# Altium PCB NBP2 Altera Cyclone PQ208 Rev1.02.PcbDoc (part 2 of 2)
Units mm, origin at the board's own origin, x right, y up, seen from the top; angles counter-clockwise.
Board outline 69 x 80.99 mm, 2 copper layers (Top Layer, Bottom Layer); 52 components, 189 nets, 558 pads, 192 vias.
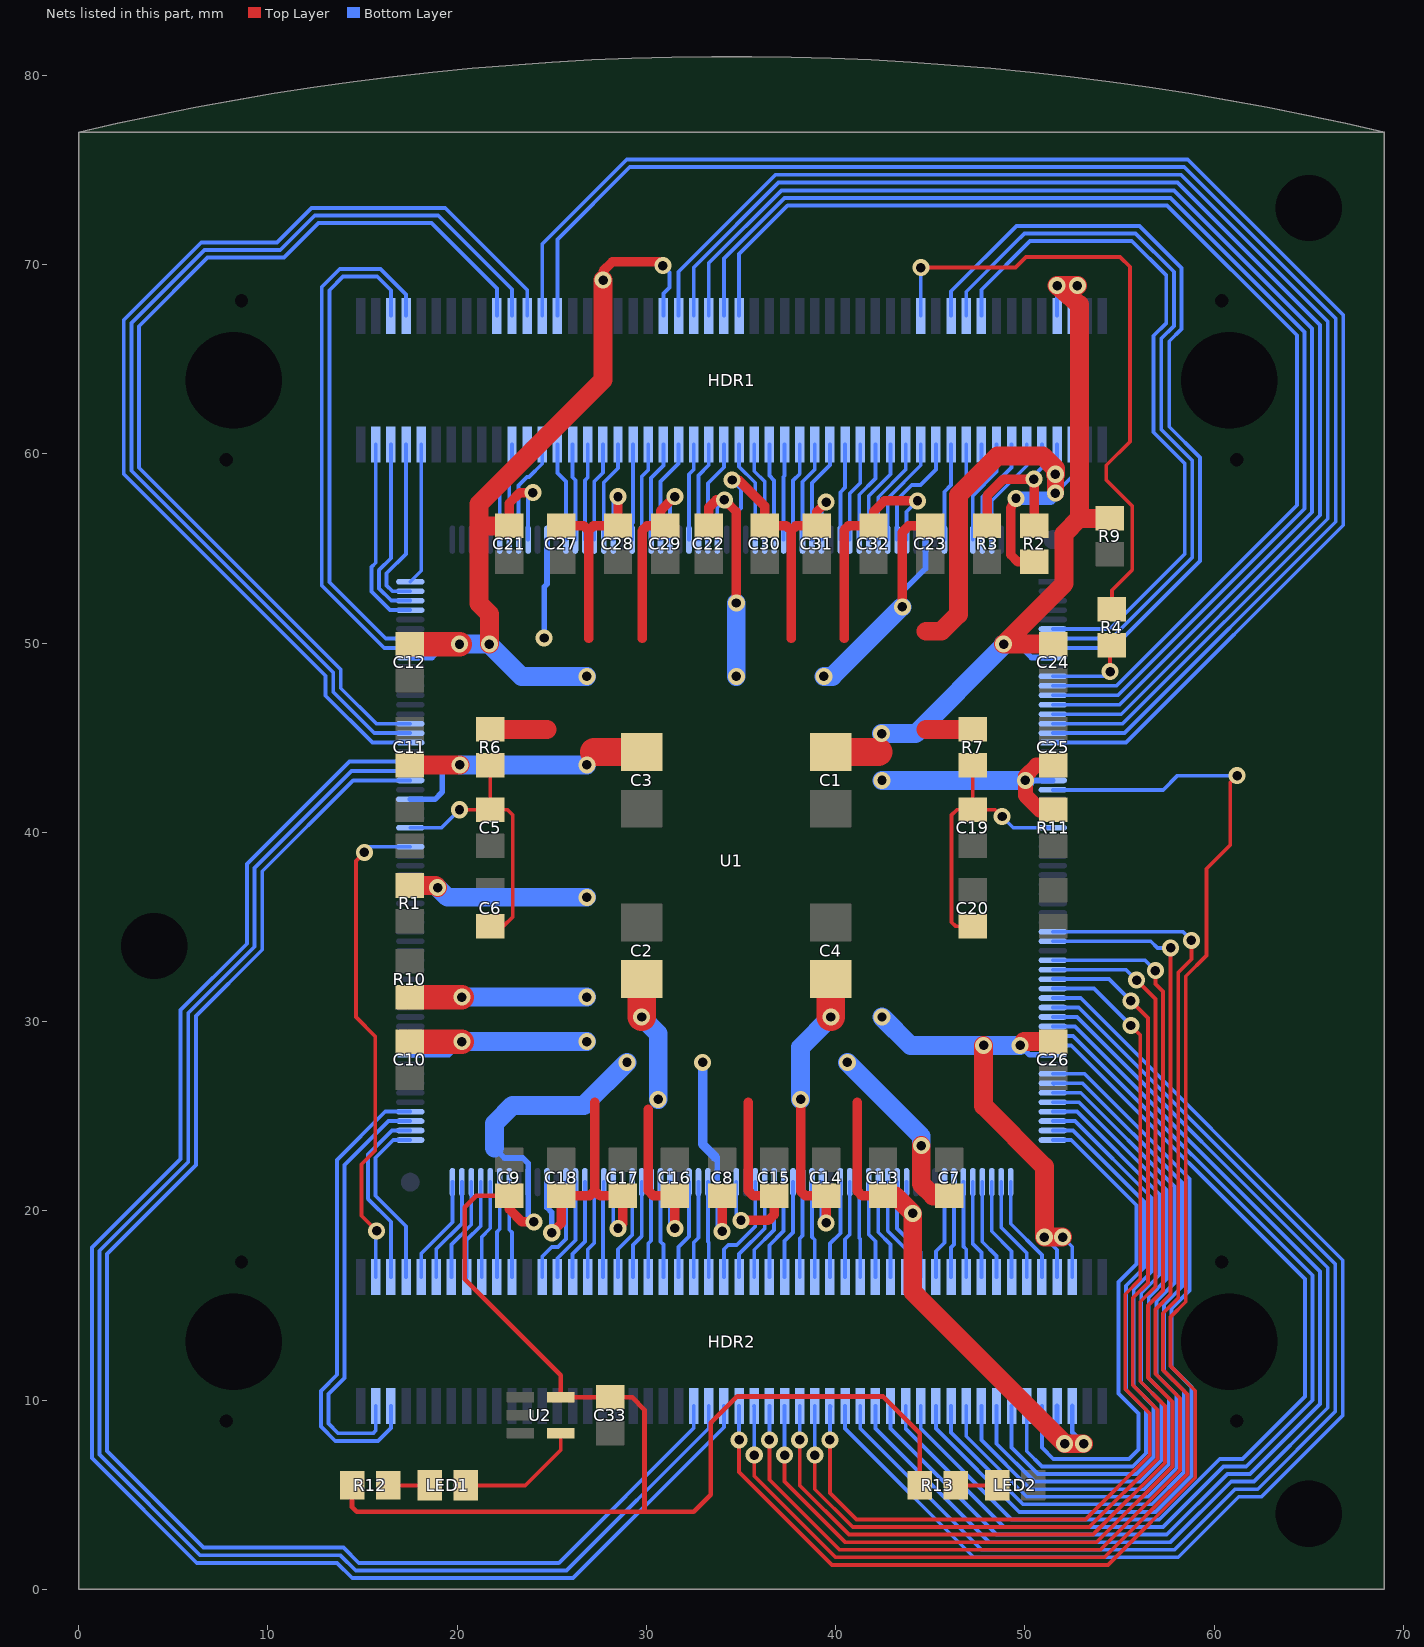
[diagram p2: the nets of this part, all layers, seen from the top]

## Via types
v1: diameter 0.9, hole 0.5, Top Layer to Bottom Layer, 192 vias

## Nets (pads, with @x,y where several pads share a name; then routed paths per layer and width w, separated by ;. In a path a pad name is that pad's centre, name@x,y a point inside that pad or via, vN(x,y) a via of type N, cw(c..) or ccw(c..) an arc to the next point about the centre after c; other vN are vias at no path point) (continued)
IO19: HDR2.45 U1.159 | length 81.4
  Bottom Layer w0.2: U1.159@17.525,42.75 14.505,42.75 9.703,37.948 9.703,33.803 6.198,30.297 6.198,22.431 1.5,17.734 1.5,7.314 6.598,2.216 13.989,2.216 14.805,1.4 25.375,1.4 32.5,8.525 HDR2.45@32.5,9.7
IO20: HDR2.47 U1.160 | length 83.8
  Bottom Layer w0.2: U1.160@17.525,43.25 14.421,43.25 9.296,38.125 9.296,33.962 5.791,30.457 5.791,22.591 1.1,17.9 1.1,7.13 6.426,1.803 13.836,1.803 14.64,1 25.781,1 33.3,8.519 HDR2.47@33.3,9.7
IO21: HDR2.49 U1.161 | length 86.1
  Bottom Layer w0.2: U1.161@17.525,43.75 14.311,43.75 8.89,38.329 8.89,34.121 5.385,30.616 5.385,22.75 0.7,18.065 0.7,6.945 6.242,1.403 13.659,1.403 14.462,0.6 26.127,0.6 34.1,8.573 HDR2.49@34.1,9.7
IO22: HDR2.51 U1.23 | length 80.7
  Top Layer w0.2: v1(34.9,7.9) 34.9,6.2 39.8,1.3 54.4,1.3 59,5.9 59,10.5 57.7,11.8 57.7,14.4 58.5,15.2 58.5,32.4 59.6,33.5 59.6,38.079 60.852,39.331 60.852,42.64 v1(61.214,43.002)
  Bottom Layer w0.2: v1(34.9,7.9) HDR2.51@34.9,9.7 ; U1.23@51.475,42.25 57.312,42.25 58.064,43.002 v1(61.214,43.002)
IO23: HDR2.53 U1.38 | length 67.1
  Top Layer w0.2: v1(35.7,7.1) 35.7,6 40,1.7 54.2,1.7 58.6,6.1 58.6,10.3 57.3,11.6 57.3,14.6 58.1,15.4 58.1,32.6 58.8,33.3 v1(58.8,34.3)
  Bottom Layer w0.2: HDR2.53@35.687,9.687 HDR2.53@35.7,9.7 v1(35.7,7.1) ; U1.38@51.475,34.75 58.35,34.75 v1(58.8,34.3)
IO24: HDR2.55 U1.39 | length 63.7
  Top Layer w0.2: v1(36.5,7.9) 36.5,5.8 40.2,2.1 54,2.1 58.2,6.3 58.2,10.1 56.9,11.4 56.9,14.8 57.7,15.6 v1(57.7,33.9)
  Bottom Layer w0.2: v1(36.5,7.9) HDR2.55@36.5,9.7 ; U1.39@51.475,34.25 56.65,34.25 57,33.9 v1(57.7,33.9)
IO25: HDR2.57 U1.41 | length 60.4
  Top Layer w0.2: v1(37.3,7.1) 37.3,5.7 40.5,2.5 53.8,2.5 57.8,6.5 57.8,9.9 56.5,11.2 56.5,15 57.3,15.8 57.3,31.6 56.9,32 v1(56.9,32.7)
  Bottom Layer w0.2: v1(37.3,7.1) HDR2.57@37.3,9.7 ; U1.41@51.475,33.25 56.35,33.25 v1(56.9,32.7)
IO26: HDR2.59 U1.42 | length 57.6
  Top Layer w0.2: v1(38.1,7.9) 38.1,5.5 40.7,2.9 53.6,2.9 57.4,6.7 57.4,9.7 56.1,11 56.1,15.2 56.9,16 56.9,31.2 v1(55.9,32.2)
  Bottom Layer w0.2: v1(38.1,7.9) HDR2.59@38.1,9.7 ; U1.42@51.475,32.75 55.35,32.75 v1(55.9,32.2)
IO27: HDR2.61 U1.43 | length 54.9
  Top Layer w0.2: v1(38.9,7.1) 38.9,5.3 40.9,3.3 53.4,3.3 57,6.9 57,9.5 55.7,10.8 55.7,15.4 56.5,16.2 56.5,30.2 v1(55.6,31.1)
  Bottom Layer w0.2: v1(38.9,7.1) HDR2.61@38.9,9.7 ; U1.43@51.475,32.25 54.45,32.25 v1(55.6,31.1)
IO28: HDR2.63 U1.44 | length 52.2
  Top Layer w0.2: v1(39.7,7.9) 39.7,5.1 41.1,3.7 53.2,3.7 56.6,7.1 56.6,9.3 55.3,10.6 55.3,15.6 56.1,16.4 56.1,29.3 v1(55.6,29.8)
  Bottom Layer w0.2: v1(39.7,7.9) HDR2.63@39.7,9.7 HDR2.63@39.725,9.675 ; U1.44@51.475,31.75 53.65,31.75 v1(55.6,29.8)
IO29: HDR2.65 U1.45 | length 62.7
  Bottom Layer w0.2: HDR2.65@40.5,9.7 40.5,8.5 47.3,1.7 58.1,1.7 61.3,4.9 62.5,4.9 66.8,9.2 66.8,17.4 52.95,31.25 U1.45@51.475,31.25
IO30: HDR2.67 U1.46 | length 60.3
  Bottom Layer w0.2: HDR2.67@41.3,9.7 41.3,8.5 47.7,2.1 57.9,2.1 61.1,5.3 62.3,5.3 66.4,9.4 66.4,17.2 52.85,30.75 U1.46@51.475,30.75
IO31: HDR2.69 U1.47 | length 57.9
  Bottom Layer w0.2: HDR2.69@42.1,9.7 42.1,8.5 48.1,2.5 57.7,2.5 60.9,5.7 62.1,5.7 66,9.6 66,17 52.75,30.25 U1.47@51.475,30.25
IO32: HDR2.71 U1.48 | length 55.6
  Bottom Layer w0.2: HDR2.71@42.9,9.7 42.9,8.5 48.5,2.9 57.5,2.9 60.7,6.1 61.9,6.1 65.6,9.8 65.6,16.8 52.65,29.75 U1.48@51.475,29.75
IO33: HDR2.73 U1.49 | length 53.2
  Bottom Layer w0.2: HDR2.73@43.7,9.7 43.7,8.5 48.9,3.3 57.3,3.3 60.5,6.5 61.7,6.5 65.2,10 65.2,16.6 52.55,29.25 U1.49@51.475,29.25
IO34: HDR2.75 U1.50 | length 50.8
  Bottom Layer w0.2: HDR2.75@44.5,9.7 44.5,8.5 49.3,3.7 57.1,3.7 60.3,6.9 61.5,6.9 64.8,10.2 64.8,16.4 52.45,28.75 U1.50@51.475,28.75
IO35: HDR2.77 U1.53 | length 43.4
  Bottom Layer w0.2: HDR2.77@45.3,9.7 45.3,8.5 49.7,4.1 56.9,4.1 58.8,6 58.8,10.7 57.75,11.75 57.75,14.85 58.7,15.8 58.7,21.7 53.15,27.25 U1.53@51.475,27.25
JIOA0: HDR1.3 U1.177 | length 10.3
  Bottom Layer w0.2: HDR1.3@15.7,60.5 15.7,54.252 15.475,54.027 15.475,52.725 16.45,51.75 U1.177@17.525,51.75
JIOA1: HDR1.5 U1.178 | length 9.8
  Bottom Layer w0.2: HDR1.5@16.5,60.5 16.5,54.486 15.875,53.861 15.875,52.891 16.516,52.25 U1.178@17.525,52.25
JIOA2: HDR1.7 U1.179 | length 9.2
  Bottom Layer w0.2: HDR1.7@17.3,60.5 17.3,54.721 16.275,53.696 16.275,53.056 16.581,52.75 U1.179@17.525,52.75
JIOA3: HDR1.9 U1.180 | length 7.5
  Bottom Layer w0.2: U1.180@17.525,53.25 18.1,53.825 HDR1.9@18.1,60.5
JIOB0: HDR1.83 U1.235 | length 5.4
  Bottom Layer w0.2: U1.235@46.75,55.475 46.75,57.872 47.7,58.822 HDR1.83@47.7,60.5
JIOB1: HDR1.85 U1.236 | length 5.5
  Bottom Layer w0.2: U1.236@47.25,55.475 47.25,57.806 48.5,59.056 HDR1.85@48.5,60.5
JIOB2: HDR1.87 U1.237 | length 5.7
  Bottom Layer w0.2: U1.237@47.75,55.475 47.75,57.74 49.3,59.291 HDR1.87@49.3,60.5
JIOB3: HDR1.89 U1.238 | length 5.8
  Bottom Layer w0.2: U1.238@48.25,55.475 48.25,57.525 50.1,59.375 HDR1.89@50.1,60.5
KBCLOCK: HDR1.22 U1.164 | length 54.4
  Bottom Layer w0.2: U1.164@17.525,45.25 15.625,45.25 13.45,47.425 13.45,48.447 2.788,59.109 2.788,66.919 6.644,70.775 10.65,70.775 12.475,72.6 19,72.6 22.9,68.7 HDR1.22@22.9,67.3
KBDATA: HDR1.24 U1.163 | length 56.7
  Bottom Layer w0.2: U1.163@17.525,44.75 15.525,44.75 13.05,47.225 13.05,48.281 2.388,58.943 2.388,67.085 6.478,71.175 10.484,71.175 12.309,73 19.375,73 23.7,68.675 HDR1.24@23.7,67.3
LCD_BCKL: HDR2.22 U1.114 | length 5.2
  Bottom Layer w0.2: U1.114@22.8,21.475 U1.114@22.75,21.525 22.75,19.006 22.9,18.856 HDR2.22@22.9,16.5
LCD_E: HDR2.26 U1.108 | length 5.7
  Bottom Layer w0.2: HDR2.26@24.5,16.5 24.5,17.6 25,18.1 25.325,18.1 25.75,18.525 U1.108@25.75,21.525
LED0: HDR2.60 U1.83 | length 5.1
  Bottom Layer w0.2: HDR2.60@38.1,16.5 38.1,18.55 38.25,18.7 U1.83@38.25,21.525
LED1: HDR2.62 U1.82 | length 5.1
  Bottom Layer w0.2: U1.82@38.75,21.525 38.75,18.625 38.9,18.475 HDR2.62@38.9,16.5
LED2: HDR2.64 U1.79 | length 5.3
  Bottom Layer w0.2: HDR2.64@39.7,16.5 39.7,18.275 40.25,18.825 U1.79@40.25,21.525
LED3: HDR2.66 U1.78 | length 5.1
  Bottom Layer w0.2: HDR2.66@40.5,16.5 40.5,18.509 40.75,18.759 U1.78@40.75,21.525
LED4: HDR2.68 U1.77 | length 5
  Bottom Layer w0.2: U1.77@41.25,21.525 41.25,18.575 41.3,18.525 HDR2.68@41.3,16.5
LED5: HDR2.70 U1.76 | length 5.2
  Bottom Layer w0.2: U1.76@41.75,21.525 41.75,18.75 42.1,18.4 HDR2.70@42.1,16.5
LED6: HDR2.72 U1.75 | length 5.3
  Bottom Layer w0.2: U1.75@42.25,21.525 42.25,18.875 42.9,18.225 HDR2.72@42.9,16.5
LED7: HDR2.74 U1.74 | length 5.4
  Bottom Layer w0.2: U1.74@42.75,21.525 42.75,18.95 43.7,18 HDR2.74@43.7,16.5
MOUSECLOCK: HDR1.26 U1.18 | length 82.6
  Bottom Layer w0.2: HDR1.26@24.5,67.3 24.5,71.1 28.959,75.559 58.604,75.559 66.825,67.338 66.825,56.233 55.342,44.75 U1.18@51.475,44.75
MOUSEDATA: HDR1.28 U1.17 | length 80.4
  Bottom Layer w0.2: HDR1.28@25.3,67.3 25.3,71.334 29.124,75.159 58.42,75.159 66.425,67.154 66.425,56.417 55.258,45.25 U1.17@51.475,45.25
NetC5_1: C5.1 C6.1 R6.2 U1.154 | length 15
  Top Layer w0.2: v1(20.125,41.2) C5.1@21.75,41.2 ; C6.1@21.75,35.05 22.452,35.05 22.936,35.535 22.936,40.919 22.656,41.2 C5.1@21.75,41.2 ; R6.2@21.75,43.55 C5.1@21.75,41.2
  Bottom Layer w0.2: U1.154@17.525,40.25 19.175,40.25 v1(20.125,41.2)
NetC19_2: C19.2 C20.2 R7.2 U1.27 | length 15.1
  Top Layer w0.2: C20.2@47.25,35.05 46.332,35.05 46.126,35.255 46.126,40.919 46.407,41.2 48.437,41.2 v1(48.793,40.843) ; C19.2@47.25,41.2 R7.2@47.25,43.55
  Bottom Layer w0.2: v1(48.793,40.843) 49.387,40.25 U1.27@51.475,40.25
NetLED1_1: LED1.1 R12.2 | length 2.2
  Top Layer w0.2: R12.2@16.35,5.5 LED1.1@18.55,5.5
NetLED1_2: LED1.2 U2.4 | length 6.7
  Top Layer w0.2: LED1.2@20.45,5.5 23.6,5.5 25.475,7.375 U2.4@25.475,8.25
NetLED2_1: LED2.1 R13.2 | length 2.2
  Top Layer w0.2: R13.2@46.35,5.5 LED2.1@48.55,5.5
NEXUS_TCK: HDR1.82 U1.7 | length 39.6
  Bottom Layer w0.2: HDR1.82@46.9,67.3 46.9,68.575 49.467,71.142 49.975,71.65 55.85,71.65 57.875,69.625 57.875,66.761 57.201,66.087 57.201,61.309 58.846,59.663 58.846,54.528 54.568,50.25 U1.7@51.475,50.25
NEXUS_TDI: HDR1.84 U1.6 | length 37.3
  Bottom Layer w0.2: HDR1.84@47.7,67.3 47.7,68.675 50.275,71.25 55.65,71.25 57.475,69.425 57.475,66.927 56.794,66.246 56.794,61.149 58.445,59.498 58.445,54.712 54.483,50.75 U1.6@51.475,50.75
NEXUS_TDO: HDR1.76 R4.2 | length 33.7
  Top Layer w0.2: v1(44.5,69.85) 49.507,69.85 50.066,70.409 55.033,70.409 55.55,69.892 55.55,60.65 54.3,59.4 54.3,58.628 55.677,57.252 55.677,53.877 54.6,52.8 R4.2@54.6,51.8
  Bottom Layer w0.2: HDR1.76@44.5,67.3 v1(44.5,69.85)
NEXUS_TDO#: R4.1 U1.11 | length 4.9
  Top Layer w0.2: v1(54.5,48.5) R4.1@54.5,50.3
  Bottom Layer w0.2: U1.11@51.475,48.25 54.25,48.25 v1(54.5,48.5)
NEXUS_TMS: HDR1.80 U1.8 | length 41.9
  Bottom Layer w0.2: HDR1.80@46.1,67.3 46.1,68.6 49.55,72.05 56.05,72.05 58.275,69.825 58.275,66.595 57.633,65.953 57.633,61.443 59.258,59.817 59.258,54.347 54.661,49.75 U1.8@51.475,49.75
RAM0_DATA0: HDR2.42 U1.98 | length 5.1
  Bottom Layer w0.2: U1.98@30.75,21.525 30.75,18.375 30.9,18.225 HDR2.42@30.9,16.5
RAM0_DATA1: HDR2.40 U1.99 | length 5.1
  Bottom Layer w0.2: HDR2.40@30.1,16.5 30.1,18.275 30.25,18.425 U1.99@30.25,21.525
RAM0_DATA2: HDR2.38 U1.100 | length 5.2
  Bottom Layer w0.2: HDR2.38@29.3,16.5 29.3,18.209 29.75,18.659 U1.100@29.75,21.525
RAM0_DATA3: HDR2.36 U1.101 | length 5.3
  Bottom Layer w0.2: HDR2.36@28.5,16.5 28.5,17.975 29.25,18.725 U1.101@29.25,21.525
RAM0_DATA4: HDR2.34 U1.104 | length 5
  Bottom Layer w0.2: HDR2.34@27.7,16.5 27.7,20.575 27.75,20.625 U1.104@27.75,21.525
RAM0_DATA5: HDR2.32 U1.105 | length 5.2
  Bottom Layer w0.2: HDR2.32@26.9,16.5 26.9,17.969 27.25,18.319 U1.105@27.25,21.525
RAM0_DATA6: HDR2.30 U1.106 | length 5.3
  Bottom Layer w0.2: HDR2.30@26.1,16.5 26.1,17.734 26.75,18.384 U1.106@26.75,21.525
RAM0_DATA7: HDR2.28 U1.107 | length 5.4
  Bottom Layer w0.2: HDR2.28@25.3,16.5 25.3,17.5 26.25,18.45 U1.107@26.25,21.525
RAM0_OE: HDR1.41 U1.202 | length 5.3
  Bottom Layer w0.2: U1.202@30.25,55.475 30.25,58.734 30.9,59.384 HDR1.41@30.9,60.5
RAM0_WE: HDR1.79 U1.233 | length 5.2
  Bottom Layer w0.2: U1.233@45.75,55.475 45.75,58.003 46.1,58.353 HDR1.79@46.1,60.5
RAM1_DATA0: HDR1.45 U1.206 | length 5.1
  Bottom Layer w0.2: U1.206@32.25,55.475 32.25,58.925 32.5,59.175 HDR1.45@32.5,60.5
RAM1_DATA1: HDR1.49 U1.208 | length 5.4
  Bottom Layer w0.2: U1.208@33.25,55.475 33.25,58.45 34.1,59.3 HDR1.49@34.1,60.5
RAM1_DATA2: HDR1.53 U1.214 | length 5.3
  Bottom Layer w0.2: HDR1.53@35.7,60.5 35.7,59.091 36.25,58.541 U1.214@36.25,55.475
RAM1_DATA3: HDR1.57 U1.216 | length 5
  Bottom Layer w0.2: U1.216@37.25,55.475 37.25,58.8 37.3,58.85 HDR1.57@37.3,60.5
RAM1_DATA4: HDR1.55 U1.215 | length 5.1
  Bottom Layer w0.2: HDR1.55@36.5,60.5 36.5,58.856 36.75,58.606 U1.215@36.75,55.475
RAM1_DATA5: HDR1.51 U1.213 | length 5.4
  Bottom Layer w0.2: HDR1.51@34.9,60.5 34.9,59.325 35.75,58.475 U1.213@35.75,55.475
RAM1_DATA6: HDR1.47 U1.207 | length 5.3
  Bottom Layer w0.2: U1.207@32.75,55.475 32.75,58.859 33.3,59.409 HDR1.47@33.3,60.5
RAM1_DATA7: HDR1.43 U1.203 | length 5.4
  Bottom Layer w0.2: U1.203@30.75,55.475 30.75,58.55 31.7,59.5 HDR1.43@31.7,60.5
RAM1_OE: HDR1.39 U1.201 | length 5.2
  Bottom Layer w0.2: U1.201@29.75,55.475 29.75,58.8 30.1,59.15 HDR1.39@30.1,60.5
RAM1_WE: HDR1.61 U1.218 | length 5.3
  Bottom Layer w0.2: U1.218@38.25,55.475 38.25,58.534 38.9,59.184 HDR1.61@38.9,60.5
RAM_ADDR0: HDR1.21 U1.186 | length 5.3
  Bottom Layer w0.2: U1.186@22.25,55.475 22.25,58.639 22.9,59.289 HDR1.21@22.9,60.5
RAM_ADDR1: HDR1.25 U1.188 | length 5.6
  Bottom Layer w0.2: U1.188@23.25,55.475 23.25,58.338 23.697,58.786 23.799,58.786 24.5,59.487 HDR1.25@24.5,60.5
RAM_ADDR2: HDR1.29 U1.194 | length 5.1
  Bottom Layer w0.2: HDR1.29@26.1,60.5 26.1,58.766 26.25,58.616 U1.194@26.25,55.475
RAM_ADDR3: HDR1.33 U1.196 | length 5.2
  Bottom Layer w0.2: U1.196@27.25,55.475 27.25,58.557 27.7,59.007 HDR1.33@27.7,60.5
RAM_ADDR4: HDR1.65 U1.222 | length 5.1
  Bottom Layer w0.2: U1.222@40.25,55.475 40.25,57.978 40.5,58.228 HDR1.65@40.5,60.5
RAM_ADDR5: HDR1.69 U1.224 | length 5.4
  Bottom Layer w0.2: U1.224@41.25,55.475 41.25,57.847 42.1,58.697 HDR1.69@42.1,60.5
RAM_ADDR6: HDR1.73 U1.226 | length 5.6
  Bottom Layer w0.2: U1.226@42.25,55.475 42.25,57.716 43.7,59.166 HDR1.73@43.7,60.5
RAM_ADDR7: HDR1.77 U1.228 | length 6.1
  Bottom Layer w0.2: U1.228@43.25,55.475 43.25,57.58 44.025,58.355 44.48,58.355 45.3,59.175 HDR1.77@45.3,60.5
RAM_ADDR8: HDR1.75 U1.227 | length 5.7
  Bottom Layer w0.2: U1.227@42.75,55.475 42.75,57.65 44.5,59.4 HDR1.75@44.5,60.5
RAM_ADDR9: HDR1.71 U1.225 | length 5.5
  Bottom Layer w0.2: U1.225@41.75,55.475 41.75,57.781 42.9,58.931 HDR1.71@42.9,60.5
RAM_ADDR10: HDR1.67 U1.223 | length 5.3
  Bottom Layer w0.2: U1.223@40.75,55.475 40.75,57.913 41.3,58.463 HDR1.67@41.3,60.5
RAM_ADDR11: HDR1.63 U1.219 | length 5.4
  Bottom Layer w0.2: U1.219@38.75,55.475 38.75,58.469 39.7,59.419 HDR1.63@39.7,60.5
RAM_ADDR12: HDR1.59 U1.217 | length 5.2
  Bottom Layer w0.2: U1.217@37.75,55.475 37.75,58.6 38.1,58.95 HDR1.59@38.1,60.5
RAM_ADDR13: HDR1.35 U1.197 | length 5.3
  Bottom Layer w0.2: U1.197@27.75,55.475 27.75,58.491 28.5,59.241 HDR1.35@28.5,60.5
RAM_ADDR14: HDR1.31 U1.195 | length 5.1
  Bottom Layer w0.2: U1.195@26.75,55.475 26.75,58.6 26.9,58.75 HDR1.31@26.9,60.5
RAM_ADDR15: HDR1.27 U1.193 | length 5.2
  Bottom Layer w0.2: HDR1.27@25.3,60.5 25.3,59 25.75,58.55 U1.193@25.75,55.475
RAM_ADDR16: HDR1.23 U1.187 | length 5.4
  Bottom Layer w0.2: U1.187@22.75,55.475 22.75,58.486 23.7,59.436 HDR1.23@23.7,60.5
RAM_CS: HDR1.37 U1.200 | length 5
  Bottom Layer w0.2: U1.200@29.25,55.475 29.25,56.325 29.3,56.375 HDR1.37@29.3,60.5
RED0: HDR1.6 U1.174 | length 26.1
  Bottom Layer w0.2: HDR1.6@16.5,67.3 16.5,68.65 15.775,69.375 13.975,69.375 13.25,68.65 13.25,53.225 16.225,50.25 U1.174@17.525,50.25
RED1: HDR1.8 U1.173 | length 28.3
  Bottom Layer w0.2: HDR1.8@17.3,67.3 17.3,68.425 15.95,69.775 13.8,69.775 12.85,68.825 12.85,53.05 16.15,49.75 U1.173@17.525,49.75
REF_CLK: HDR2.4 U1.152 | length 26.3
  Top Layer w0.2: v1(15.1,38.95) 14.65,38.5 14.65,30.245 15.672,29.224 15.672,23.19 14.948,22.466 14.948,19.752 v1(15.75,18.95)
  Bottom Layer w0.2: v1(15.1,38.95) 15.35,39.25 U1.152@17.525,39.25 ; HDR2.4@15.7,16.5 15.7,18.9 v1(15.75,18.95)
SCL: HDR2.5 U1.124 | length 24.8
  Bottom Layer w0.2: HDR2.5@16.5,9.7 16.5,8.525 15.821,7.846 13.561,7.846 12.8,8.606 12.8,10.493 13.65,11.343 13.65,22.7 16.2,25.25 U1.124@17.525,25.25
SDA: HDR2.3 U1.123 | length 22.5
  Bottom Layer w0.2: HDR2.3@15.7,9.7 15.7,8.4 15.55,8.25 13.722,8.25 13.2,8.772 13.2,10.328 14.05,11.178 14.05,22.425 16.375,24.75 U1.123@17.525,24.75
SP0: HDR2.79 U1.54 | length 41.2
  Bottom Layer w0.2: HDR2.79@46.1,9.7 46.1,8.3 49.9,4.5 56.7,4.5 58.4,6.2 58.4,10.5 57.35,11.55 57.35,15.05 58.3,16 58.3,21.5 53.05,26.75 U1.54@51.475,26.75 U1.54@51.525,26.7
SP1: HDR2.81 U1.55 | length 38.9
  Bottom Layer w0.2: HDR2.81@46.9,9.7 46.9,8.1 50.1,4.9 56.5,4.9 58,6.4 58,10.3 56.95,11.35 56.95,15.25 57.9,16.2 57.9,21.3 52.95,26.25 U1.55@51.475,26.25
SP2: HDR2.83 U1.56 | length 36.6
  Bottom Layer w0.2: HDR2.83@47.7,9.7 47.7,7.9 50.3,5.3 56.3,5.3 57.6,6.6 57.6,10.1 56.55,11.15 56.55,15.45 57.5,16.4 57.5,21.1 52.85,25.75 U1.56@51.475,25.75
SP3: HDR2.85 U1.57 | length 34.3
  Bottom Layer w0.2: HDR2.85@48.5,9.7 48.5,7.7 50.5,5.7 56.1,5.7 57.2,6.8 57.2,9.9 56.15,10.95 56.15,15.65 57.1,16.6 57.1,20.9 52.75,25.25 U1.57@51.475,25.25
SP4: HDR2.87 U1.58 | length 32.1
  Bottom Layer w0.2: HDR2.87@49.3,9.7 49.3,7.5 50.7,6.1 55.9,6.1 56.8,7 56.8,9.7 55.75,10.75 55.75,15.85 56.7,16.8 56.7,20.7 52.65,24.75 U1.58@51.475,24.75
SP5: HDR2.89 U1.59 | length 29.8
  Bottom Layer w0.2: HDR2.89@50.1,9.7 50.1,7.3 50.9,6.5 55.7,6.5 56.4,7.2 56.4,9.5 55.35,10.55 55.35,16.05 56.3,17 56.3,20.5 52.55,24.25 U1.59@51.475,24.25
SP6: HDR2.91 U1.60 | length 27.3
  Bottom Layer w0.2: HDR2.91@50.9,9.7 50.9,7.5 51.5,6.9 55.5,6.9 56,7.4 56,9.3 54.95,10.35 54.95,16.25 55.9,17.2 55.9,20.3 52.45,23.75 U1.60@51.475,23.75
SP7: HDR2.92 U1.61 | length 5.7
  Bottom Layer w0.2: U1.61@49.25,21.525 49.25,19.325 50.9,17.675 HDR2.92@50.9,16.5
SP8: HDR2.90 U1.62 | length 5.6
  Bottom Layer w0.2: U1.62@48.75,21.525 48.75,19.125 50.1,17.775 HDR2.90@50.1,16.5
SP9: HDR2.88 U1.63 | length 5.5
  Bottom Layer w0.2: U1.63@48.25,21.525 48.25,18.925 49.3,17.875 HDR2.88@49.3,16.5
SP10: HDR2.86 U1.64 | length 5.3
  Bottom Layer w0.2: U1.64@47.75,21.525 47.75,18.375 48.5,17.625 HDR2.86@48.5,16.5
SP11: HDR2.84 U1.65 | length 5.2
  Bottom Layer w0.2: U1.65@47.25,21.525 47.25,18.25 47.7,17.8 HDR2.84@47.7,16.5
SP12: HDR2.82 U1.66 | length 5.1
  Bottom Layer w0.2: U1.66@46.75,21.525 46.75,18.125 46.9,17.975 HDR2.82@46.9,16.5
SP13: HDR2.80 U1.67 | length 5.1
  Bottom Layer w0.2: HDR2.80@46.1,16.5 46.1,18.075 46.25,18.225 U1.67@46.25,21.525
SP14: HDR2.78 U1.68 | length 5.2
  Bottom Layer w0.2: HDR2.78@45.3,16.5 45.3,17.875 45.75,18.325 U1.68@45.75,21.525
SP15: HDR2.76 U1.73 | length 5.5
  Bottom Layer w0.2: U1.73@43.25,21.525 43.25,19.075 44.5,17.825 HDR2.76@44.5,16.5
SPI_CLK: HDR1.46 U1.15 | length 69.2
  Bottom Layer w0.2: HDR1.46@32.5,67.3 32.5,69.859 36.986,74.346 58.064,74.346 65.6,66.81 65.6,56.761 55.089,46.25 U1.15@51.475,46.25
SPI_DIN: HDR1.44 U1.16 | length 71.4
  Bottom Layer w0.2: HDR1.44@31.7,67.3 31.7,69.625 36.827,74.752 58.242,74.752 66,66.994 66,56.577 55.173,45.75 U1.16@51.475,45.75
SPI_DOUT: HDR1.50 U1.13 | length 64.7
  Bottom Layer w0.2: HDR1.50@34.1,67.3 34.1,70.328 37.299,73.527 57.69,73.527 64.775,66.441 64.775,57.104 54.921,47.25 U1.13@51.475,47.25
SPI_MODE: HDR1.52 U1.12 | length 62.5
  Bottom Layer w0.2: HDR1.52@34.9,67.3 34.9,70.562 37.464,73.127 57.517,73.127 64.375,66.269 64.375,57.288 54.837,47.75 U1.12@51.475,47.75
SPI_SEL: HDR1.48 U1.14 | length 66.9
  Bottom Layer w0.2: HDR1.48@33.3,67.3 33.3,70.094 37.133,73.927 57.874,73.927 65.175,66.626 65.175,56.92 55.005,46.75 U1.14@51.475,46.75
SW0: HDR2.44 U1.95 | length 5.3
  Bottom Layer w0.2: HDR2.44@31.7,16.5 31.7,18.1 32.25,18.65 U1.95@32.25,21.525
SW1: HDR2.46 U1.94 | length 5.1
  Bottom Layer w0.2: HDR2.46@32.5,16.5 32.5,18.334 32.75,18.584 U1.94@32.75,21.525
SW2: HDR2.48 U1.93 | length 5
  Bottom Layer w0.2: U1.93@33.25,21.525 33.25,18.375 33.3,18.325 HDR2.48@33.3,16.5
SW3: HDR2.50 U1.88 | length 6
  Bottom Layer w0.2: HDR2.50@34.1,16.5 34.1,17.975 34.325,18.2 34.775,18.2 35.75,19.175 U1.88@35.75,21.525
SW4: HDR2.52 U1.87 | length 5.6
  Bottom Layer w0.2: HDR2.52@34.9,16.5 34.9,17.725 36.25,19.075 U1.87@36.25,21.525
SW5: HDR2.54 U1.86 | length 5.5
  Bottom Layer w0.2: HDR2.54@35.7,16.5 35.7,17.95 36.75,19 U1.86@36.75,21.525
SW6: HDR2.56 U1.85 | length 5.3
  Bottom Layer w0.2: HDR2.56@36.5,16.5 36.5,18.184 37.25,18.934 U1.85@37.25,21.525
SW7: HDR2.58 U1.84 | length 5.2
  Bottom Layer w0.2: HDR2.58@37.3,16.5 37.3,18.419 37.75,18.869 U1.84@37.75,21.525
SWC0: HDR2.18 U1.116 | length 5.2
  Bottom Layer w0.2: HDR2.18@21.3,16.5 21.3,18.633 21.75,19.083 U1.116@21.75,21.525
SWC1: HDR2.16 U1.117 | length 5.3
  Bottom Layer w0.2: HDR2.16@20.5,16.5 20.5,18.46 21.25,19.21 U1.117@21.25,21.525
SWC2: HDR2.14 U1.118 | length 5.5
  Bottom Layer w0.2: HDR2.14@19.7,16.5 19.7,18.226 20.75,19.276 U1.118@20.75,21.525
SWC3: HDR2.6 U1.122 | length 9.7
  Bottom Layer w0.2: HDR2.6@16.5,16.5 16.5,19.431 15.291,20.64 15.291,22.981 16.559,24.25 U1.122@17.525,24.25
SWR0: HDR2.20 U1.115 | length 5.1
  Bottom Layer w0.2: HDR2.20@22.1,16.5 22.1,18.889 22.25,19.039 U1.115@22.25,21.525
SWR1: HDR2.12 U1.119 | length 5.6
  Bottom Layer w0.2: HDR2.12@18.9,16.5 18.9,17.991 20.25,19.341 U1.119@20.25,21.525
SWR2: HDR2.10 U1.120 | length 5.7
  Bottom Layer w0.2: HDR2.10@18.1,16.5 18.1,17.757 19.75,19.407 U1.120@19.75,21.525
SWR3: HDR2.8 U1.121 | length 9.2
  Bottom Layer w0.2: HDR2.8@17.3,16.5 17.3,19.197 15.691,20.806 15.691,22.816 16.625,23.75 U1.121@17.525,23.75
TEST: HDR1.81 U1.234 | length 5.3
  Bottom Layer w0.2: U1.234@46.25,55.475 46.25,57.938 46.9,58.588 HDR1.81@46.9,60.5
VCC: C1.1 C3.1 C7.1 C8.1 C9.1 C10.1 C11.1 C12.1 C21.2 C22.2 C23.2 C24.2 C25.2 C26.2 C33.1 HDR1.34 HDR1.42 HDR1.94 HDR1.96 HDR2.94 HDR2.96 R1.1 R9.1 R10.1 R11.1 R12.1 R13.1 U1.9 U1.22 U1.51 U1.70 U1.92 U1.112 U1.130 U1.157 U1.172 U1.189 U1.209 U1.231 U2.5 | length 317.7
  Top Layer w0.25: R12.1@14.45,5.5 14.45,4.35 14.7,4.1 32.5,4.1 33.4,5 33.4,8.8 34.8,10.2 42.5,10.2 44.45,8.25 R13.1@44.45,5.5 ; C9.1@22.75,20.8 21,20.8 20.4,20.2 20.4,16.4 25.475,11.325 U2.5@25.475,10.15 29.25,10.15 29.9,9.5 29.9,4.1
  Top Layer w0.5: C9.1@22.75,20.8 22.75,20.1 23.425,19.425 v1(24.05,19.425) ; C21.2@22.75,56.2 22.75,57.396 23.317,57.963 v1(24.003,57.963) ; v1(27.711,69.19) 27.711,69.667 28.194,70.15 30.675,70.15 v1(30.875,69.95) ; C22.2@33.3,56.2 33.3,57.175 33.7,57.575 v1(34.125,57.575) 34.75,56.95 v1(34.75,52.125) ; v1(34,18.925) C8.1@34,20.8 ; v1(43.525,51.925) 43.525,55.875 43.85,56.2 C23.2@45,56.2
  Top Layer w0.8: R11.1@51.5,41.2 50.775,41.2 50.025,41.95 50.025,42.975 50.6,43.55 C25.2@51.5,43.55
  Top Layer w1: R1.1@17.5,37.2 18.858,37.2 v1(18.974,37.084) ; C11.1@17.5,43.55 17.525,43.575 v1(20.15,43.575) ; 21.15,56.2 C21.2@22.75,56.2 ; v1(21.7,49.95) 21.7,51.55 21.15,52.1 21.15,57.353 27.711,63.915 v1(27.711,69.19) ; v1(44.525,23.45) 44.525,21.425 45.15,20.8 C7.1@46,20.8 ; v1(47.821,28.746) 47.821,25.554 51.029,22.346 v1(51.029,18.618) v1(51.994,18.618) ; v1@49.95,28.95 C26.2@51.5,28.95 ; C24.2@51.5,49.95 v1(48.875,49.95) 52.07,53.145 52.07,54.559 52.07,55.778 52.883,56.591 ; v1(52.775,68.9) v1(51.7,68.9) 52.883,67.894 52.883,56.591 ; R9.1@54.483,56.601 52.883,56.591
  Top Layer w1.3: C10.1@17.5,28.95 v1(20.25,28.95) ; R10.1@17.5,31.3 v1(20.25,31.3) ; C12.1@17.5,49.95 v1(20.125,49.95)
  Top Layer w1.5: 27.25,44.25 C3.1@29.75,44.25 ; C1.1@39.75,44.25 42.25,44.25
  Bottom Layer w0.2: U1.189@23.75,55.475 23.75,57.71 v1(24.003,57.963) ; HDR1.34@27.7,67.3 27.7,69.325 v1(27.711,69.19) ; v1(30.875,69.95) 31.225,69.6 31.225,68.8 30.9,68.475 HDR1.42@30.9,67.3 ; U1.92@33.75,21.525 33.75,19.175 v1(34,18.925) ; U1.209@33.75,55.475 33.75,57.2 v1(34.125,57.575) ; v1(51.029,18.618) 51.7,17.947 HDR2.94@51.7,16.5 ; HDR1.94@51.7,67.3 v1(51.7,68.9) ; v1(51.994,18.618) 52.5,18.112 HDR2.96@52.5,16.5 ; HDR1.96@52.5,67.3 52.5,68.625 v1(52.775,68.9)
  Bottom Layer w0.3: U1.130@17.525,28.25 19.55,28.25 v1(20.25,28.95) ; U1.157@17.525,41.75 18.825,41.75 19.21,42.135 19.21,43.235 19.55,43.575 v1(20.15,43.575) ; U1.172@17.525,49.25 18.675,49.25 19.375,49.95 v1(20.125,49.95) ; 21.977,23.327 22.505,22.8 23.475,22.8 23.75,22.525 U1.112@23.75,21.525 23.75,19.725 v1(24.05,19.425) ; 33.65,22.839 33.75,22.739 U1.92@33.75,21.525 ; v1(43.525,51.925) 43.525,52.725 44.75,53.95 U1.231@44.75,55.475 ; v1(44.525,23.45) 44.75,23.225 U1.70@44.75,21.525 ; v1(48.875,49.95) 49.65,49.95 50.35,49.25 U1.9@51.475,49.25 ; v1(49.75,28.75) 50.25,28.25 U1.51@51.475,28.25 ; v1(50.025,42.75) U1.22@51.475,42.75
  Bottom Layer w0.5: v1(32.975,27.85) 32.975,23.514 33.65,22.839
  Bottom Layer w1: v1(18.974,37.084) 19.482,36.576 v1@26.848,36.576 ; v1(20.125,49.95) v1(21.7,49.95) 23.4,48.25 v1(26.85,48.25) ; v1(20.15,43.575) v1(26.85,43.575) ; v1(20.25,28.95) v1(26.85,28.95) ; v1(20.25,31.3) v1(26.85,31.3) ; 21.977,23.327 21.977,24.627 22.925,25.575 26.7,25.575 v1(28.975,27.85) ; v1(34.75,48.25) v1(34.75,52.125) ; v1(39.375,48.25) 39.825,48.25 v1@43.5,51.925 ; v1(40.625,27.85) 44.525,23.95 v1(44.525,23.45) ; v1(42.425,45.225) 44.225,45.225 48.75,49.75 v1(48.875,49.95) ; v1(42.45,30.25) 43.95,28.75 v1(47.821,28.746) v1(49.75,28.75) ; v1(42.45,42.75) v1(50.025,42.75)
  other v1: 26.85,36.576
VCCINT: C2.1 C4.1 C13.1 C14.1 C15.1 C16.1 C17.1 C18.1 C27.2 C28.2 C29.2 C30.2 C31.2 C32.2 HDR1.93 HDR1.95 HDR2.93 HDR2.95 R2.1 R6.1 R7.1 U1.72 U1.81 U1.90 U1.97 U1.103 U1.110 U1.191 U1.198 U1.204 U1.211 U1.220 U1.229 | length 187.2
  Top Layer w0.5: v1(25,18.85) 25.5,19.35 C18.1@25.5,20.8 27,20.8 27.275,21.075 ; C27.2@25.5,56.2 26.7,56.2 26.95,55.95 ; 26.95,50.25 26.95,55.95 ; 27.275,25.75 27.275,21.075 ; v1(28.5,19.075) 28.75,19.325 C17.1@28.75,20.8 27.55,20.8 27.275,21.075 ; v1(28.5,57.75) C28.2@28.5,56.2 27.2,56.2 26.95,55.95 ; 29.775,50.25 29.775,55.95 30.025,56.2 C29.2@30.75,56.2 ; 30.1,25.375 30.1,21.075 30.375,20.8 C16.1@31.5,20.8 v1(31.5,19.075) ; C29.2@31,56.2 C29.2@30.75,56.2 ; v1(31.5,57.75) 30.75,57 C29.2@30.75,56.2 ; v1(34.525,58.625) 34.875,58.625 36.25,57.25 C30.2@36.25,56.2 37.4,56.2 37.65,55.95 ; v1(35,19.5) 36.45,19.5 36.75,19.8 C15.1@36.75,20.8 35.65,20.8 35.375,21.075 35.375,25.75 ; 37.65,50.25 37.65,55.95 ; v1(38.15,25.9) 38.15,21.05 38.4,20.8 C14.1@39.5,20.8 v1(39.5,19.375) ; v1(39.5,57.45) 39,56.95 C31.2@39,56.2 37.9,56.2 37.65,55.95 ; 40.45,50.25 40.45,55.975 40.675,56.2 C32.2@42,56.2 42,56.95 42.575,57.525 v1(44.325,57.525) ; 41.15,25.75 41.15,21.05 41.4,20.8 C13.1@42.5,20.8 ; v1(49.53,57.658) 49.25,57.15 49.25,54.675 49.625,54.3 R2.1@50.5,54.3
  Top Layer w0.9: v1(51.613,57.928) v1(51.613,58.928)
  Top Layer w1: R6.1@21.75,45.45 24.75,45.45 ; C13.1@42.5,20.8 43.15,20.8 v1(44.075,19.875) 44.075,15.725 v1(52.1,7.7) v1(53.1,7.7) ; 44.775,45.45 R7.1@47.25,45.45 ; 44.775,50.633 45.593,50.633 46.482,51.522 46.482,57.822 48.56,59.9 50.946,59.9 51.613,59.233 v1(51.613,58.928)
  Top Layer w1.5: v1(29.75,30.25) C2.1@29.75,32.25 ; v1(39.75,30.25) C4.1@39.75,32.25
  Bottom Layer w0.2: U1.103@28.25,21.525 28.25,19.325 v1(28.5,19.075) ; U1.198@28.25,55.475 28.25,57.5 v1(28.5,57.75) ; U1.97@31.25,21.525 31.25,19.325 v1(31.5,19.075) ; U1.204@31.25,55.475 31.25,57.5 v1(31.5,57.75) ; v1(34.525,58.625) 35,58.15 35,57.15 34.75,56.9 U1.211@34.75,55.475 ; U1.90@34.75,21.525 34.75,19.75 v1(35,19.5) ; U1.81@39.25,21.525 39.25,19.625 v1(39.5,19.375) ; U1.220@39.25,55.475 39.25,57.2 v1(39.5,57.45) ; U1.72@43.75,21.525 43.75,20.225 v1(44.075,19.875) ; U1.229@43.75,55.475 43.75,56.95 v1(44.325,57.525) ; v1(51.613,57.928) 52.5,58.815 HDR1.95@52.5,60.5 ; HDR1.93@51.7,60.5 v1@51.714,58.928
  Bottom Layer w0.25: HDR2.93@51.7,9.7 51.7,8.1 v1(52.1,7.7) ; HDR2.95@52.5,9.7 52.5,8.3 v1(53.1,7.7)
  Bottom Layer w0.3: v1(24.6,50.275) 24.6,52.978 24.75,53.128 U1.191@24.75,55.475 ; U1.110@24.75,21.525 24.75,20.175 25,19.925 v1(25,18.85)
  Bottom Layer w0.7: v1(49.53,57.658) 51.343,57.658 v1(51.613,57.928)
  Bottom Layer w1: v1(29.75,30.25) 30.625,29.375 v1(30.625,25.9) ; v1(38.15,25.9) 38.15,28.65 v1(39.75,30.25)
VDRIVE: HDR1.20 U1.165 | length 52
  Bottom Layer w0.2: U1.165@17.525,45.75 15.725,45.75 13.85,47.625 13.85,48.612 3.188,59.275 3.188,66.753 6.809,70.375 10.85,70.375 12.675,72.2 18.65,72.2 22.1,68.75 HDR1.20@22.1,67.3
VREF: HDR1.91 R2.2 R3.1 | length 8.9
  Top Layer w0.5: R3.1@48,56.2 48,57.8 48.875,58.675 v1(50.47,58.674) 50.5,58.644 R2.2@50.5,56.2
  Bottom Layer w0.2: v1@50.47,58.852 50.9,59.282 HDR1.91@50.9,60.5
  Bottom Layer w0.23: v1(50.47,58.674) v1@50.47,58.852
pads on no net: HDR1.56 HDR1.MH1 HDR1.MH2 HDR1.MH3 HDR1.MH4 HDR1.MH5 HDR1.MH6 HDR2.MH1 HDR2.MH2 HDR2.MH3 HDR2.MH4 HDR2.MH5 HDR2.MH6 U1.19 U1.20 U1.21 U1.24 U1.32 U1.37 U1.162 U1.239 U1.240 U1.FID1 U1.FID2 U2.1

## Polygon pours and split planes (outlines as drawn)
GND on Top Layer "Top Layer-GND" (solid, remove dead copper, pour order 1000): 0,0 69,0 69,81 0,81
GND on Bottom Layer "Bottom Layer-GND" (solid, remove dead copper, pour order 1001): 0,0 69,0 69,81 0,81

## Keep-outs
Top Layer:
  lines w0.8: 0,0 69,0
Keep-Out Layer:
  lines w0.8: 0,0 0,77 cw(c34.5,-69.801) 69,77 69,0 26.5,0 26.4,-0.1 14.2,-0.1 14.1,0 0,0

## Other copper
Top Layer:
  rectangle net VCC: 41.425,28.35 43.15,47.725
  rectangle net VCC: 27.2,46.325 43.15,48.925
  rectangle net VCC: 27.45,27.175 43.15,28.95
  rectangle net VCC: 26.1,27.175 28.05,48.925
  rectangle net VCCINT: 43.725,25.875 45.225,49.875
  rectangle net VCCINT: 23.925,49.45 45.2,51.15
  rectangle net VCCINT: 25.475,25.25 45.225,26.675
  rectangle net VCCINT: 23.925,25.25 25.575,49.675

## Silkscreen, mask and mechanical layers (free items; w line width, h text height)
Bottom Overlay:
  drawing of 850 lines, arcs and shapes, not listed
  text "REV 1.02" at 47.6,76.5 h1.3
  text "NBP2" at 54.5,76.5 h1.3
  text "1" at 13.97,58.42 h1
  text "1" at 14.224,7.62 h1
PCB Boundary:
  the board outline again, w0.25
  text "PCB boundary coincides with centre-line of tracks" at 0,-12 h0.75
Gerber ID:
  text ".Layer_Name" at 0,-6 h0.75
Printout ID:
  text ".Printout_Name" at 0,-10 h0.75
Drill Drawing:
  text ".Legend" at 0,-8 h0.75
